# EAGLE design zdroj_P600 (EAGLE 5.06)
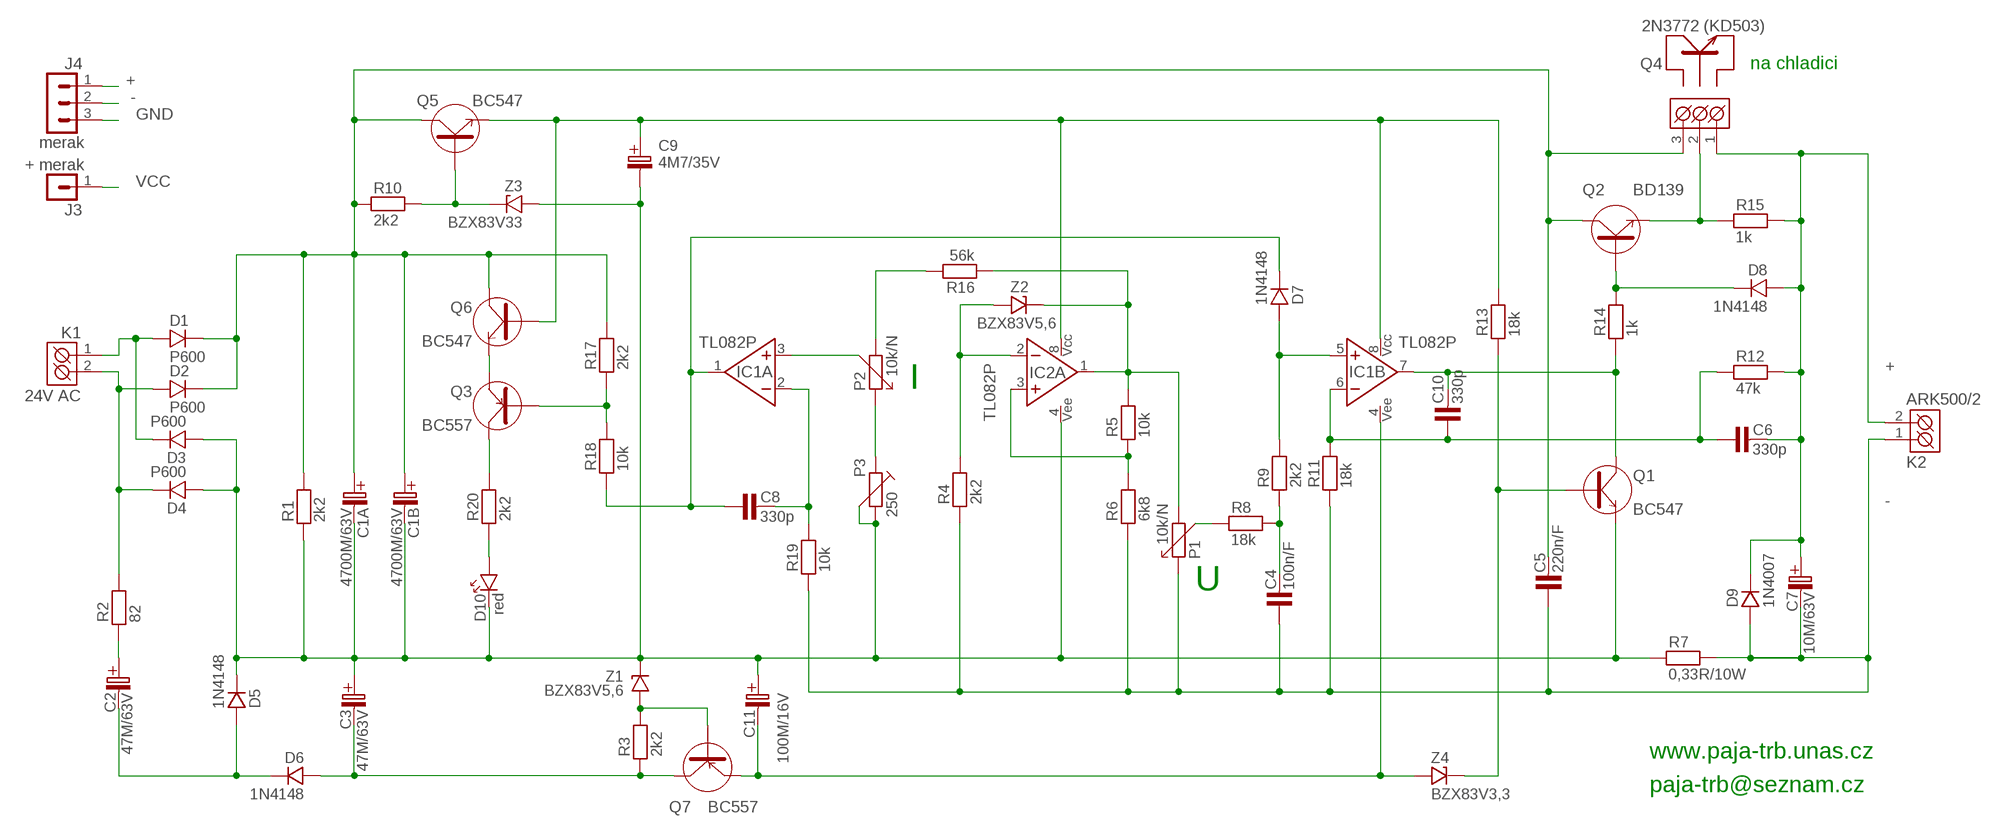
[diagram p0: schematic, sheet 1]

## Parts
C1A  4700M/63V  [C_EL12,5]
C1B  4700M/63V  [C_EL12,5]
C2  47M/63V  [C_EL_3,5]
C3  47M/63V  [C_EL_3,5]
C4  100n/F  100N-K/100  [RM5_3,2]
C5  220n/F  220N-K/63V  [RM5_3,2]
C6  330p  C-KERAMIK_SMD_1206  [1206]
C7  10M/63V  [C_EL_2]
C8  330p  C-KERAMIK_SMD_1206  [1206]
C9  4M7/35V  4M7/50V  [C_EL_2]
C10  330p  C-KERAMIK_SMD_1206  [1206]
C11  100M/16V  [C_EL_2,5]
D1  P600  D_P6  [P6]
D2  P600  D_P6  [P6]
D3  P600  D_P6  [P6]
D4  P600  D_P6  [P6]
D5  1N4148  1N4148_7,5  [DO35]
D6  1N4148  1N4148_7,5  [DO35]
D7  1N4148  1N4148_7,5  [DO35]
D8  1N4148  1N4148_7,5  [DO35]
D9  1N4007  1N4007_10  [DO41]
D10  red  LED_5  [LED_5]
IC1  TL082P  TL072  [DIL8]
IC2  TL082P  TL072  [DIL8]
J3  + merak  S1G1_JUMP  [S1G1_JUM]
J4  merak  S1G3_JUMP  [S1G3_JUM]
K1  24V AC  ARK500/2  [ARK500/2]
K2  ARK500/2  [ARK500/2]
P1  10k/N  PC16ML"  [PC16ML]
P2  10k/N  PC16ML"  [PC16ML]
P3  250  TRIMRPT10V  [PT10V]
Q1  BC547  BC546  [TO-92]
Q2  BD139  BD139_STOJ  [TO-126S]
Q3  BC557  BC556  [TO-92]
Q4  2N3772 (KD503)  ARK500/3  [ARK500/3]
Q5  BC547  BC546  [TO-92]
Q6  BC547  BC546  [TO-92]
Q7  BC557  BC556  [TO-92]
R1  2k2  W2_2K2  [R__2W]
R2  82  R_7,5  [R-7,5]
R3  2k2  R_7,5  [R-7,5]
R4  2k2  R_SMD_1206  [1206]
R5  10k  R_SMD_1206  [1206]
R6  6k8  R_SMD_1206  [1206]
R7  0,33R/10W  R__10W  [R-_10W]
R8  18k  R_10  [R-10]
R9  2k2  R_7,5  [R-7,5]
R10  2k2  R_7,5  [R-7,5]
R11  18k  R_7,5  [R-7,5]
R12  47k  R_7,5  [R-7,5]
R13  18k  R_10  [R-10]
R14  1k  R_7,5  [R-7,5]
R15  1k  R_7,5  [R-7,5]
R16  56k  R_SMD_1206  [1206]
R17  2k2  R_7,5  [R-7,5]
R18  10k  R_7,5  [R-7,5]
R19  10k  R_10  [R-10]
R20  2k2  R_SMD_1206  [1206]
Z1  BZX83V5,6  D-ZENEROVA_0,5W_BZX83V  [DO35]
Z2  BZX83V5,6  D-ZENEROVA_0,5W_BZX83V  [DO35]
Z3  BZX83V33  D-ZENEROVA_0,5W_BZX83V  [DO35]
Z4  BZX83V3,3  D-ZENEROVA_2W_BZY  [DO41]

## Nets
+: C6.2 C7.C+(C_EL+) D8.A D9.K J4.1 K2.2(K2) Q4.1(K1) R12.2 R15.2
-: C4.1 C5.1 C7.C-(C_EL-) D9.A J4.2 K2.1(K1) P1.1 R4.1 R6.1 R7.2 R11.1 R19.1
GND: C1A.C-(C_EL-) C1B.C-(C_EL-) C3.C+(C_EL+) C9.C-(C_EL-) C11.C+(C_EL+) D3.A D4.A D5.K D10.K IC2.4(NS:VEE) J4.3 P3.2 P3.3 Q1.3(E) R1.1 R7.1 Z1.K Z3.A
N$2: Q3.1(C) R20.2
N$3: C2.C+(C_EL+) R2.1
N$5: C2.C-(C_EL-) D5.A D6.K
N$6: C3.C-(C_EL-) D6.A Q7.1(C) R3.1
N$8: C11.C-(C_EL-) IC1.4(NS:VEE) Q7.3(E) Z4.A
N$9: C8.1 D7.K IC1.1(A:VYSTUP) R18.1
N$10: IC1.3(A:NEIN+) P2.3
N$11: Q5.2(B) R10.2 Z3.K
N$12: D10.A R20.1
N$13: Q3.3(E) Q6.3(E)
N$14: P1.3 R8.1
N$15: Q3.2(B) R17.1 R18.2
N$17: C9.C+(C_EL+) IC1.8(NS:VCC) IC2.8(NS:VCC) Q5.3(E) Q6.2(B) R13.2
N$18: C8.2 IC1.2(A:IN-) R19.2
N$19: P2.1 P3.1
N$22: IC2.2(A:IN-) R4.2 Z2.A
N$23: IC2.3(A:NEIN+) R5.1 R6.2
N$24: IC2.1(A:VYSTUP) P1.2 R5.2 R16.1 Z2.K
N$25: P2.2 R16.2
N$27: C4.2 R8.2 R9.1
N$28: D7.A IC1.5(B:NEIN+) R9.2
N$29: C6.1 C10.1 IC1.6(B:IN-) R11.2 R12.1
N$31: C10.2 IC1.7(B:VYSTUP) Q1.1(C) R14.1
N$32: Q1.2(B) R13.1 Z4.K
N$33: Q2.1(E) Q4.2(K2) R15.1
N$36: D8.K Q2.3(B) R14.2
STRID1: D1.A D3.K K1.1(K1)
STRID2: D2.A D4.K K1.2(K2) R2.2
VCC: C1A.C+(C_EL+) C1B.C+(C_EL+) C5.2 D1.K D2.K J3.1 Q2.2(C) Q4.3(K3) Q5.1(C) Q6.1(C) R1.2 R10.1 R17.2
Z1: Q7.2(B) R3.2 Z1.A
Unconnected: IC2.5(B:NEIN+) IC2.6(B:IN-) IC2.7(B:VYSTUP)

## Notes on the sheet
- na chladici
- I
- U
- www.paja-trb.unas.cz
- paja-trb@seznam.cz

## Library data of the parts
C1A C1B = #PaJa_C-el_2:4700M/63V
C2 C3 = #PaJa_C-el_2:47M/63V
C4 = #PaJa_C-folie:100N-K/100
C5 = #PaJa_C-folie:220N-K/63V
C6 C8 C10 = #PaJa_23_e56:C-KERAMIK: Kondenzator - keramicky
C7 = #PaJa_C-el_2:10M/63V
C9 = #PaJa_C-el_2:4M7/50V
C11 = #PaJa_C-el_2:100M/16V
D1-D4 = #PaJa_23_e56:D: Dioda - univerzální
D5-D8 = #PaJa_23_e56:1N4148: Univerzalni dioda - 0,15A, 75V
D9 = #PaJa_23_e56:1N4007: Usmernovaci dioda - 1A, 1000V
D10 = #PaJa_23_e56:LED: LED - jednobarevna
IC1 IC2 = #PaJa_23_e56:TL072: OZ - JFET - 2x
J3 = #PaJa_23_e56:S1G1_JUMP: Radove konektory - koliky - 1x
J4 = #PaJa_23_e56:S1G3_JUMP: Radove konektory - koliky - 3x
K1 K2 = #PaJa_23_e56:ARK500/2: Svorkovnice - roztec 5mm - dvojita
P1 P2 = #PaJa_23_e56:PC16ML: Potenciometr - plastovy - mono - 100R az 5M
P3 = #PaJa_23_e56:TRIMR: Trimr
Q1 Q5 Q6 = #PaJa_23_e56:BC546: Tranzistor NPN - Univerzalni NF - Ic=0,1A
Q2 = #PaJa_23_e56:BD139: Tranzistor NPN - Vykonovy - Ic=1,5A
Q3 Q7 = #PaJa_23_e56:BC556: Tranzistor PNP - Univerzalni NF - Ic=0,1A
Q4 = #PaJa_23_e56:ARK500/3: Svorkovnice - roztec 5mm - trojita
R1 = #PaJa_R:W2_2K2
R2-R20 = #PaJa_23_e56:R: Rezistor
Z1-Z4 = #PaJa_23_e56:D-ZENEROVA: Zenerova dioda

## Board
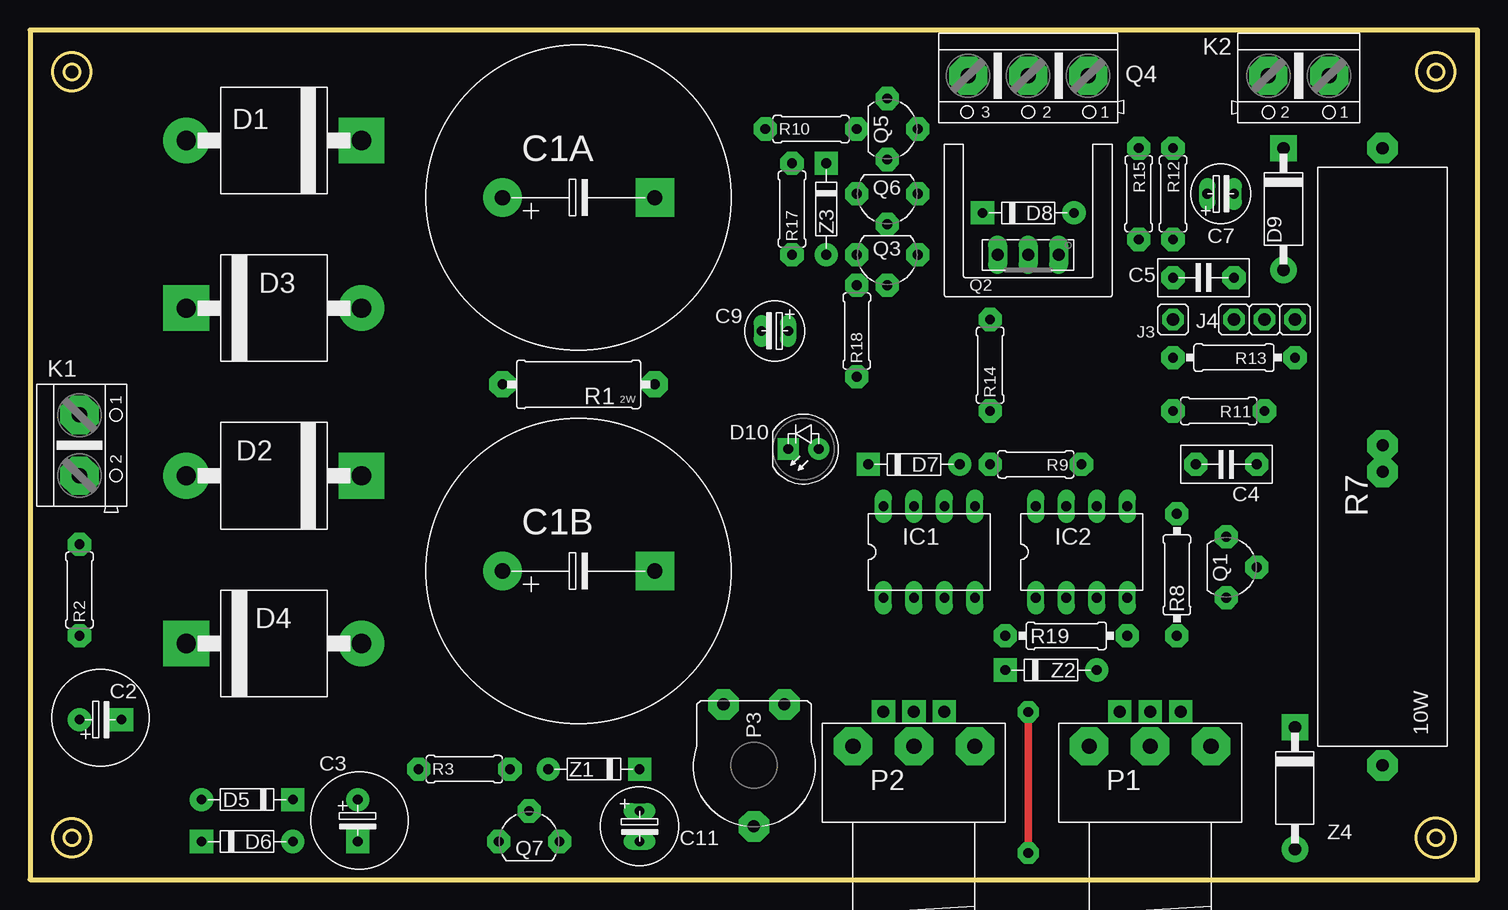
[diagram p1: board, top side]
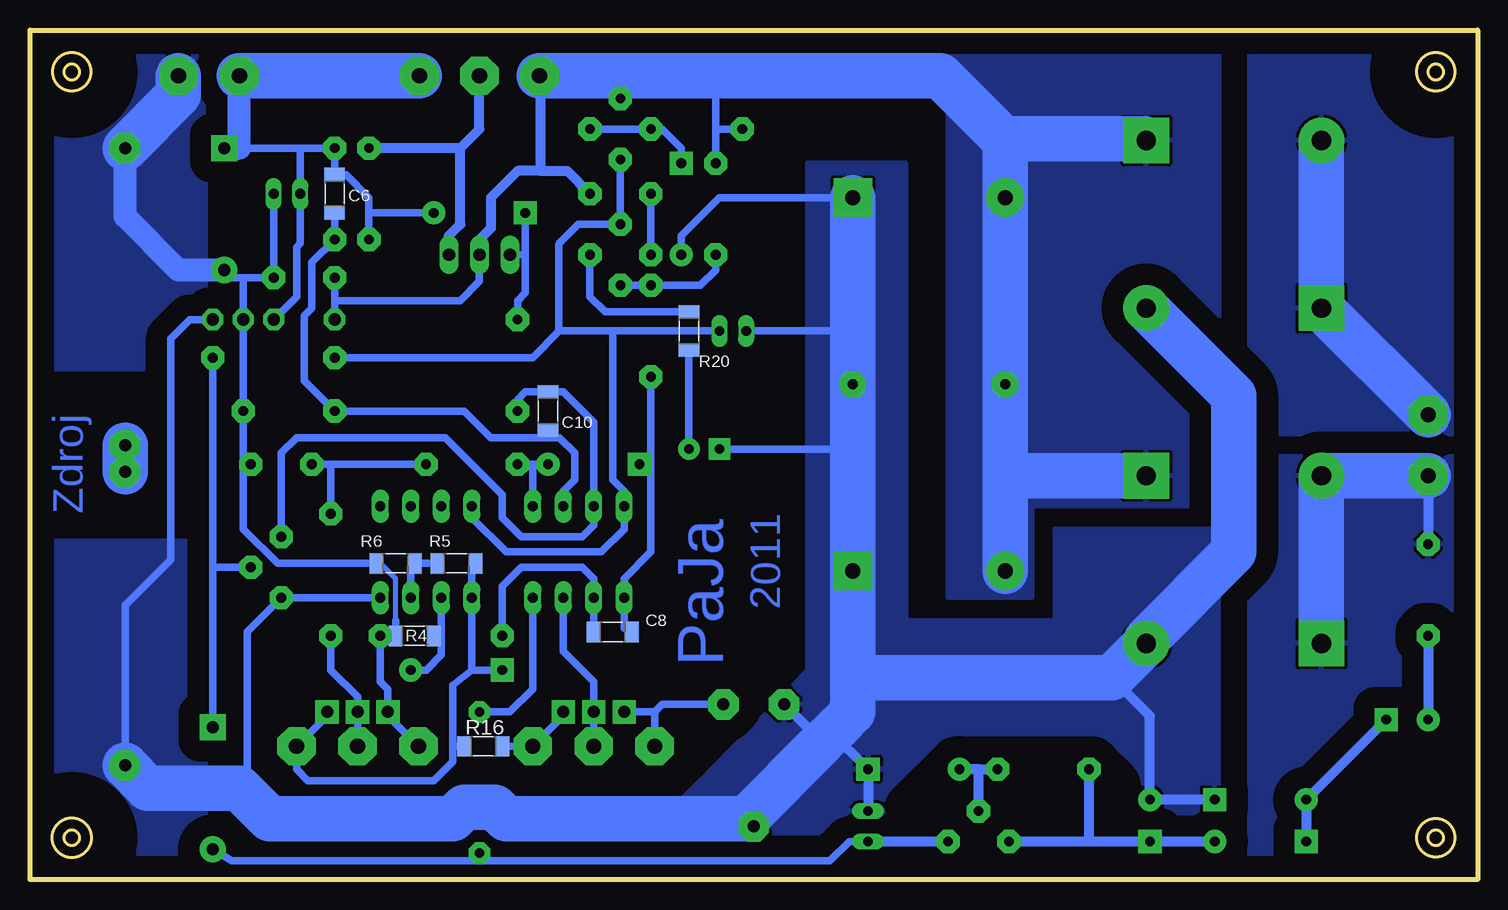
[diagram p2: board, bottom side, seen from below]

Size 120.64 x 70.79 mm. Coordinates in mm from the lower left corner, seen from the top.
Outline: 0,0 120.64,0 120.64,70.79 0,70.79 0,0
Outline: circle at 117.16,67.31 radius 1.59
Outline: circle at 117.16,67.31 radius 0.64
Outline: circle at 117.16,3.49 radius 0.64
Outline: circle at 117.16,3.49 radius 1.62
Outline: circle at 3.49,3.49 radius 0.64
Outline: circle at 3.49,3.49 radius 1.59
Outline: circle at 3.49,67.31 radius 0.64
Outline: circle at 3.49,67.31 radius 1.59
Copper layers (1*16): Top 0.035mm / dielectric 1.5mm / Bottom 0.035mm
Design rules "default": minimum track width 10mil, minimum drill 24mil, track to track 8mil, track to pad 8mil, pad to pad 8mil, via to via 8mil, smd to smd 8mil, copper to edge 40mil, drill to drill 8mil, minimum pad ring 10mil, minimum via ring 8mil, stop-mask expansion 4mil, vias tented up to drill 0mil, thermal gap 10mil
Holes 3.2 mm at 3.49,3.49 3.49,67.31 117.16,67.31 117.16,3.49
bRestrict: area 0,63.8 to 7,70.8; area 0,0 to 7,7; area 113.7,0 to 120.7,7; area 113.7,63.8 to 120.7,70.8; 6 lines

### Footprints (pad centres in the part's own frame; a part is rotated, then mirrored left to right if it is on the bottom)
C_EL12,5 = drill 1.27 pad 3.2 round: C+ -6.35,0 | drill 1.27 pad 3.2 square: C- 6.35,0
C_EL_3,5 = drill 0.813 pad 1.93 round: C+ 0,0 | drill 0.813 pad 1.93 square: C- 3.493,0
RM5_3,2 = drill 0.813 pad 1.93 octagon: 1 -2.54,0; 2 2.54,0
1206 = smd 1.143 x 1.702: 1 -1.587,0; 2 1.587,0
C_EL_2 = drill 0.813 pad 1.27 long: C+ 0,0; C- 2.223,0
C_EL_2,5 = drill 0.813 pad 1.27 long: C+ -1.27,0; C- 1.27,0
P6 = drill 1.6 pad 3.81 round: A -7.303,0 | drill 1.6 pad 3.81 square: K 7.303,0
DO35 = drill 0.813 pad 1.93 round: A -3.81,0 | drill 0.813 pad 1.93 square: K 3.81,0
DO41 = drill 1.016 pad 2.184 round: A -5.08,0 | drill 1.016 pad 2.184 square: K 5.08,0
LED_5 = drill 0.813 pad 1.778 round: A -1.27,0 | drill 0.813 pad 1.778 square: K 1.27,0
DIL8 = drill 0.813 pad 1.4 long: 1 -3.81,-3.81; 2 -1.27,-3.81; 3 1.27,-3.81; 4 3.81,-3.81; 5 3.81,3.81; 6 1.27,3.81; 7 -1.27,3.81; 8 -3.81,3.81
S1G1_JUM = drill 1.016 pad 1.778 octagon: 1 0,0
S1G3_JUM = drill 1.016 pad 1.778 octagon: 1 -2.54,0; 2 0,0; 3 2.54,0
ARK500/2 = drill 1.27 pad 3.2 octagon: 1 -2.54,0; 2 2.54,0
PC16ML = drill 1.27 pad 3.2 octagon: 1 -5.08,0; 2 5.08,0; 3 0,0
PT10V = drill 1.016 pad 2.54 octagon: 1 -2.54,-5.08; 2 0,5.08; 3 2.54,-5.08
TO-92 = drill 0.813 pad 1.93 octagon: 1 0,2.54; 2 2.54,0; 3 0,-2.54
TO-126S = drill 1.016 pad 1.6 long: 1 -2.54,0; 2 0,0; 3 2.54,0
ARK500/3 = drill 1.27 pad 3.2 octagon: 1 -5,0; 2 0,0; 3 5,0
R__2W = drill 0.813 pad 2.184 octagon: 1 -6.35,0; 2 6.35,0
R-7,5 = drill 0.813 pad 1.93 octagon: 1 -3.81,0; 2 3.81,0
R-_10W = drill 1.016 pad 2.54 octagon: 1 -25.718,0; 2 25.718,0
R-10 = drill 0.813 pad 1.93 octagon: 1 -5.08,0; 2 5.08,0

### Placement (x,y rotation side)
C1A  45.72,56.83 0 top
C1B  45.72,25.72 0 top
C2  4.13,13.34 0 top
C3  27.3,6.67 270 top
C4  99.69,34.61 180 top
C5  97.79,50.16 180 top
C6  95.25,57.15 90 bottom
C7  98.11,57.15 0 top
C8  72.07,20.64 180 bottom
C9  63.18,45.72 180 top
C10  77.47,39.05 90 bottom
C11  50.8,4.45 270 top
CHLAD  [CH_DO1_S]  83.19,48.58 180 top
D1  20.32,61.59 0 top
D2  20.32,33.66 0 top
D3  20.32,47.62 180 top
D4  20.32,19.68 180 top
D5  18.1,6.67 0 top
D6  18.1,3.17 180 top
D7  73.66,34.61 180 top
D8  83.19,55.56 180 top
D9  104.46,55.88 90 top
D10  64.45,35.88 180 top
IC1  74.93,27.3 0 top
IC2  87.63,27.3 0 top
J3  95.25,46.67 0 top
J4  102.87,46.67 0 top
K1  4.13,36.2 270 top
K2  105.73,66.99 180 top
P1  93.34,11.11 0 top
P2  73.66,11.11 0 top
P3  60.32,9.53 180 top
Q1  99.69,26.04 0 top
Q2  83.19,52.07 180 top
Q3  71.44,52.07 270 top
Q4  83.19,66.99 180 top
Q5  71.44,62.55 0 top
Q6  71.44,57.15 270 top
Q7  41.59,3.17 90 top
R1  45.72,41.27 180 top
R2  4.13,24.13 90 top
R3  36.2,9.21 0 top
R4  88.58,20.32 0 bottom
R5  85.09,26.35 0 bottom
R6  90.17,26.35 0 bottom
R7  112.71,35.24 90 top
R8  95.57,25.4 90 top
R9  83.82,34.61 180 top
R10  65.09,62.55 0 top
R11  99.06,39.05 180 top
R12  95.25,57.15 90 top
R13  100.33,43.5 180 top
R14  80.01,42.86 90 top
R15  92.39,57.15 270 top
R16  82.87,11.11 0 bottom
R17  63.5,55.88 90 top
R18  68.9,45.72 90 top
R19  86.36,20.32 180 top
R20  65.72,45.72 90 bottom
Z1  46.99,9.21 0 top
Z2  85.09,17.46 180 top
Z3  66.36,55.88 90 top
Z4  105.41,7.62 90 top

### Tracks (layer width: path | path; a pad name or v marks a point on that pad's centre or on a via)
+
  Bottom 0.61: 98.11,60.96 R12.2 C6.2 94.3,58.74 92.39,56.83 92.39,55.56 | 98.11,60.96 D9.K | D8.A 92.39,55.56 | 92.39,55.56 R15.2 | 98.11,60.96 C7.C+ 98.11,53.02 98.42,52.7 98.42,48.58 J4.1
  Bottom 1.93: K2.2 103.19,60.96 D9.K
  Bottom 3.81: K2.2 Q4.1
-  (via drill 1 pad 1.93)
  Bottom 0.406: 90.17,21.59 90.17,25.08 91.44,26.35 R6.1
  Bottom 0.61: R6.1 100.01,26.35 102.87,29.21 102.87,34.61 | 90.17,21.59 R4.1 R19.1 91.44,16.51 90.8,15.88 v90.8,13.97 90.8,13.65 P1.1 | 102.87,50.16 C5.1 C7.C- | 102.87,50.16 104.46,50.16 D9.A | 102.87,50.16 J4.2 R11.1 102.87,36.83 102.87,34.61 | 102.87,34.61 C4.1
  Bottom 1.93: R7.2 112.71,55.24 108.27,50.8 D9.A
  Bottom 3.81: K2.1 108.27,65.41 R7.2
  pour Bottom (isolate 1.778): 120.65,70.8 106.05,70.8 106.05,42.55 120.65,42.55
A  (via drill 1 pad 2.54)
  Bottom 3.81: v112.71,33.97 v112.71,36.2
GND
  Bottom 0.61: IC2.4 Q1.3 102.55,20.64 102.55,8.26 103.19,7.62 | 52.07,45.72 C9.C- | 52.07,35.88 D10.K | C1A.C- 63.18,56.83 66.36,53.66 Z3.A | 60.96,5.08 P3.2 | R7.1 112.71,22.86 108.9,26.67 108.9,45.09 107.31,46.67 J4.3
  Bottom 0.813: D5.K C3.C+ 27.3,13.65 30.48,16.83 | C11.C+ Z1.K 53.98,12.38 53.66,12.7 53.34,12.7 | 54.61,11.43 P3.3
  Bottom 3.81: C1A.C- 52.07,45.72 R1.1 52.07,35.88 C1B.C- 52.07,16.83 | R7.1 110.81,7.62 103.19,7.62 100.65,5.08 85.41,5.08 84.45,6.03 81.92,6.03 80.96,5.08 60.96,5.08 54.61,11.43 53.34,12.7 52.07,13.97 52.07,16.83 | 52.07,16.83 30.48,16.83 D4.A 27.62,20 20.32,27.3 20.32,40.32 D3.A
  pour Bottom (isolate 1.778): 21.59,0 21.59,29.21 35.24,29.21 35.24,21.59 47.62,21.59 47.62,59.69 55.88,59.69 55.88,17.46 64.77,8.26 66.36,6.67 66.36,0 64.77,0
  pour Bottom (isolate 1.778): 120.65,0 120.65,28.26 106.05,28.26 106.05,0
N$2
  Bottom 0.61: R20.2 72.71,47.31 73.98,48.58 Q3.1
N$3
  Bottom 0.813: R2.1 C2.C+
N$5
  Bottom 0.813: D6.K D5.A C2.C-
N$6
  Bottom 0.813: 32.38,3.17 Q7.1 | D6.A C3.C- 32.38,3.17 | 32.38,3.17 R3.1
N$8  (via drill 0.81 pad 1.78)
  Top 0.61: v83.19,2.22 v83.19,13.97
  Bottom 0.406: 83.19,1.59 v83.19,2.22
  Bottom 0.61: C11.C- 52.39,3.17 53.98,1.59 83.19,1.59 103.82,1.59 Z4.A | IC1.4 78.74,15.88 80.64,13.97 v83.19,13.97
  Bottom 0.813: Q7.3 C11.C-
N$9
  Bottom 0.61: C8.1 71.12,20.95 IC1.1 71.12,25.08 68.9,27.3 68.9,34.61 | 68.9,34.61 R18.1 | 68.9,34.61 D7.K
N$10  (via drill 1 pad 1.93)
  Bottom 0.61: IC1.3 76.2,19.05 73.66,16.51 v73.66,13.97 P2.3
N$11
  Bottom 0.61: R10.2 68.58,62.55 | R10.2 Q5.2 | Z3.K 66.36,60.96 67.95,62.55 R10.2
N$12
  Bottom 0.61: D10.A R20.1
N$13
  Bottom 0.61: Q3.3 Q6.3
N$14  (via drill 1 pad 1.93)
  Bottom 0.61: R8.1 95.57,17.46 93.35,15.24 v93.35,13.97 P1.3
N$15
  Bottom 0.61: Q3.2 R18.2 64.77,49.53 63.5,50.8 R17.1
N$17
  Bottom 0.61: IC2.8 83.82,30.16 80.96,27.3 73.02,27.3 71.12,29.21 IC1.8 71.12,32.38 72.07,33.34 72.07,45.72 | Q5.3 Q6.2 74.93,54.61 76.52,53.02 76.58,52.88 76.58,45.72 76.52,45.72 | 72.07,45.72 C9.C+ | 72.07,45.72 76.52,45.72 | 76.52,45.72 78.74,43.5 R13.2
N$18
  Bottom 0.61: R19.2 81.28,24.45 79.69,26.04 74.61,26.04 73.66,25.08 IC1.2 C8.2
N$19  (via drill 1 pad 1.93)
  Bottom 0.61: P3.1 67.95,14.61 68.58,13.97 | 68.58,13.97 P2.1 | 68.58,13.97 v71.12,13.97
N$22
  Bottom 0.61: 86.36,20.32 IC2.2 | 86.36,20.32 R4.2 | 86.36,20.32 86.36,18.73 87.63,17.46 Z2.A
N$23
  Bottom 0.61: IC2.3 88.9,26.04 R6.2 R5.1
N$24  (via drill 1 pad 1.93)
  Bottom 0.61: R5.2 83.82,26.04 IC2.1 83.82,17.46 | 83.82,17.46 Z2.K | 85.41,11.11 85.41,9.84 87,8.26 97.47,8.26 98.42,9.21 P1.2 95.89,13.65 v95.89,13.97 | 85.41,11.11 85.41,16.19 83.82,17.46 | R16.1 85.41,11.11
N$25  (via drill 1 pad 1.93)
  Bottom 0.61: R16.2 P2.2 76.2,13.65 v76.2,13.97
N$27
  Bottom 0.61: R9.1 95.57,34.61 | 95.57,34.61 C4.2 | 95.57,34.61 R8.2
N$28
  Bottom 0.61: D7.A 78.42,34.61 | 78.42,34.61 R9.2 | IC1.5 78.74,34.29 78.42,34.61
N$29
  Bottom 0.61: IC1.6 76.2,32.38 75.25,33.34 75.25,35.56 76.52,36.83 77.47,36.83 | R12.1 C6.1 R12.1 | R12.1 97.16,51.44 97.16,47.62 97.79,46.99 97.79,41.59 R11.2 84.45,39.05 82.23,36.83 77.47,36.83 | 77.47,36.83 C10.1
N$31
  Bottom 0.61: Q1.1 99.69,35.56 98.42,36.83 86.04,36.83 81.28,32.07 81.28,30.16 79.69,28.57 74.61,28.57 73.66,29.53 IC1.7 73.66,38.1 76.2,40.64 C10.2 79.38,40.64 80.01,40.01 R14.1
N$32
  Bottom 0.61: Z4.K 105.41,26.04 | 105.41,26.04 R13.1 | 105.41,26.04 Q1.2
N$33
  Bottom 0.813: Q4.2 83.19,62.55 84.77,60.96 | 84.77,60.96 R15.1 | Q2.1 85.73,53.66 84.77,54.61 84.77,60.96
N$36
  Bottom 0.61: 79.38,52.07 Q2.3 | 79.38,52.07 D8.K | 79.38,52.07 79.38,48.9 80.01,48.26 R14.2
STRID1
  Bottom 3.81: D1.A D3.K K1.1
  pour Bottom (isolate 1.778): 0,70.8 19.05,70.8 19.05,37.15 0,37.15
STRID2
  Bottom 0.813: K1.2 R2.2
  Bottom 3.81: K1.2 D2.A D4.K
  pour Bottom (isolate 1.778): 0,35.24 19.05,35.24 19.05,0 0,0
VCC
  Bottom 0.406: Q4.3 78.1,66.91
  Bottom 0.61: Q2.2 83.19,49.85 84.77,48.26 95.25,48.26 | 71.44,66.99 Q5.1 | 95.25,48.26 C5.2 | 63.5,66.99 63.5,62.55 | 63.5,62.55 R17.2 | 63.5,62.55 R10.1 | 95.25,48.26 J3.1
  Bottom 0.813: Q2.2 83.19,53.34 82.23,54.29 82.23,56.83 80.01,59.05 78.1,59.05 | Q6.1 75.88,59.05 78.1,59.05 | 78.1,66.91 78.1,59.05
  Bottom 3.81: Q4.3 71.44,66.99 63.5,66.99 44.77,66.99 39.53,61.75 | 39.37,33.66 C1B.C+ | 39.37,33.66 R1.2 C1A.C+ 39.37,61.59 39.53,61.75 | D1.K 27.78,61.75 39.53,61.75 | D2.K 39.37,33.66
  pour Bottom (isolate 1.778): 21.59,70.8 21.59,31.11 37.15,31.11 37.15,23.5 44.13,23.5 44.13,70.8
Z1
  Bottom 0.813: 41.59,9.21 R3.2 | 41.59,9.21 Z1.A | Q7.2 41.59,9.21

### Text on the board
Bottom: Zdroj | 2011 | PaJa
